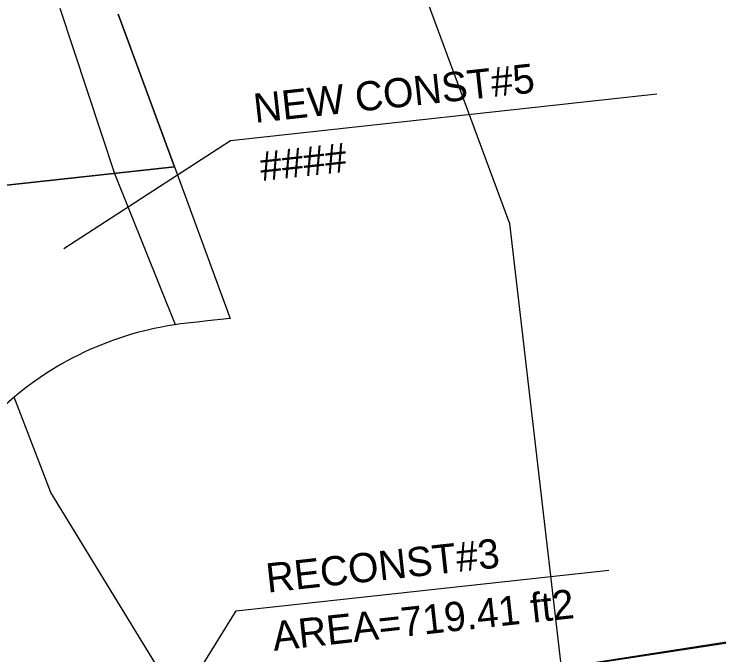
# Model space of a CAD drawing. Extents: x 1509538 to 1510847, y 401283 to 402022.
# Drawn here: x 1509818.6 to 1509886.2, y 401626.4 to 401687.8 of the extents above; entities that cross this region are included whole.
import ezdxf

# ---------------------------------------------------------------- set-up
doc = ezdxf.new("R2010")
doc.units = 0
for name, color, linetype in [('LAWE_P_T', 7, 'Continuous'), ('Level 24', 7, 'Continuous'), ('Level 25', 7, 'Continuous'), ('Level 3', 7, 'Continuous'), ('Level 4', 7, 'Continuous'), ('Level 5', 7, 'Continuous'), ('Level 7', 7, 'Continuous')]:
    doc.layers.add(name, color=color, linetype=linetype)

msp = doc.modelspace()

# ---------------------------------------------------------------- linework, layer by layer
at = {"layer": 'LAWE_P_T'}
for points in [[(1509823.397, 401665.344), (1509839.375, 401675.681), (1509880.206, 401680.132)], [(1509821.018, 401600.097), (1509839.911, 401630.638), (1509875.612, 401634.53)]]:
    msp.add_lwpolyline(points, dxfattribs=at)
at = {"layer": 'Level 24'}
msp.add_lwpolyline([(1509829.75, 401765.911), (1509866.097, 401667.732), (1509876.615, 401577.466), (1509875.566, 401568.188), (1509883.853, 401563.183), (1509866.769, 401506.877), (1509856.531, 401476.729), (1509809.074, 401412), (1509809.101, 401403.538), (1509796.557, 401386.395), (1509783.485, 401379.525), (1509778.168, 401371.598), (1509774.096, 401368.359), (1509767.585, 401349.346), (1509764.231, 401344.649), (1509737.941, 401349.46)], dxfattribs=at)
at = {"layer": 'Level 25'}
msp.add_lwpolyline([(1510026.788, 401648.904), (1510037.691, 401640.619), (1510051.798, 401629.899), (1510058.051, 401624.503), (1509984.136, 401613.929), (1509867.795, 401596.154), (1509863.727, 401624.032)], close=True, dxfattribs=at)
at = {"layer": 'Level 3'}
msp.add_lwpolyline([(1509823.042, 401688.327), (1509828.278, 401672.51), (1509834.078, 401658.053), (1509834.087, 401658.032), (1509834, 401658.02), (1509833.385, 401657.921), (1509832.772, 401657.81), (1509832.062, 401657.666), (1509831.554, 401657.552), (1509831.019, 401657.422), (1509830.473, 401657.28), (1509829.89, 401657.115), (1509829.31, 401656.939), (1509828.733, 401656.752), (1509828.16, 401656.553), (1509827.591, 401656.344), (1509827.026, 401656.123), (1509826.466, 401655.891), (1509825.911, 401655.649), (1509825.36, 401655.395), (1509824.814, 401655.131), (1509824.274, 401654.856), (1509823.739, 401654.571), (1509823.209, 401654.275), (1509822.686, 401653.969), (1509822.169, 401653.653), (1509821.658, 401653.326), (1509821.153, 401652.99), (1509820.403, 401652.463), (1509819.81, 401652.023), (1509819.203, 401651.549), (1509818.648, 401651.093)], dxfattribs=at)
at = {"layer": 'Level 4'}
for points in [[(1510068.151, 401655.21), (1510017.641, 401647.51), (1509967.631, 401640.04), (1509894.451, 401628.81), (1509861.081, 401623.62)], [(1509818.648, 401651.093), (1509817.594, 401650.166), (1509817.117, 401649.717), (1509816.54, 401649.147), (1509816.084, 401648.676), (1509815.468, 401648.006), (1509814.978, 401647.444)], [(1509863.366, 401606.462), (1509861.826, 401615.769), (1509838.993, 401621.028), (1509832.572, 401624.959), (1509822.152, 401641.967), (1509818.648, 401651.093)]]:
    msp.add_lwpolyline(points, dxfattribs=at)
at = {"layer": 'Level 5'}
for p, q in [((1509828.611, 401687.769), (1509834.002, 401673.134)), ((1509834.002, 401673.134), (1509828.611, 401687.769)), ((1509834.002, 401673.134), (1509774.898, 401666.69)), ((1509774.898, 401666.69), (1509834.002, 401673.134))]:
    msp.add_line(p, q, dxfattribs=at)
at = {"layer": 'Level 7'}
for p, q in [((1509774.898, 401666.69), (1509834, 401673.138)), ((1509834, 401673.138), (1509839.345, 401658.628)), ((1509837.164, 401658.39), (1509836.17, 401658.282)), ((1509839.345, 401658.628), (1509837.164, 401658.39)), ((1509832.062, 401657.666), (1509831.554, 401657.552)), ((1509832.772, 401657.81), (1509832.062, 401657.666)), ((1509833.385, 401657.921), (1509832.772, 401657.81)), ((1509834, 401658.02), (1509833.385, 401657.921)), ((1509834.616, 401658.106), (1509834, 401658.02)), ((1509835.235, 401658.18), (1509834.616, 401658.106)), ((1509836.17, 401658.282), (1509835.235, 401658.18)), ((1509829.89, 401657.115), (1509829.31, 401656.939)), ((1509830.473, 401657.28), (1509829.89, 401657.115)), ((1509831.019, 401657.422), (1509830.473, 401657.28)), ((1509831.554, 401657.552), (1509831.019, 401657.422)), ((1509827.591, 401656.344), (1509827.026, 401656.123)), ((1509828.16, 401656.553), (1509827.591, 401656.344)), ((1509828.733, 401656.752), (1509828.16, 401656.553)), ((1509829.31, 401656.939), (1509828.733, 401656.752)), ((1509825.911, 401655.649), (1509825.36, 401655.395)), ((1509826.466, 401655.891), (1509825.911, 401655.649)), ((1509827.026, 401656.123), (1509826.466, 401655.891)), ((1509824.814, 401655.131), (1509824.274, 401654.856)), ((1509825.36, 401655.395), (1509824.814, 401655.131)), ((1509823.209, 401654.275), (1509822.686, 401653.969)), ((1509823.739, 401654.571), (1509823.209, 401654.275)), ((1509824.274, 401654.856), (1509823.739, 401654.571)), ((1509822.169, 401653.653), (1509821.658, 401653.326)), ((1509822.686, 401653.969), (1509822.169, 401653.653)), ((1509821.153, 401652.99), (1509820.403, 401652.463)), ((1509821.658, 401653.326), (1509821.153, 401652.99)), ((1509820.403, 401652.463), (1509819.81, 401652.023)), ((1509819.203, 401651.549), (1509818.648, 401651.093)), ((1509819.81, 401652.023), (1509819.203, 401651.549))]:
    msp.add_line(p, q, dxfattribs=at)

# ---------------------------------------------------------------- texts
at = {"layer": 'LAWE_P_T'}
for s, height, p in [('NEW CONST#5', 2.79999, (1509841.738, 401677.347)), ('####', 2.8, (1509842.345, 401671.78)), ('RECONST#3', 2.8, (1509842.933, 401632.375)), ('AREA=719.41 ft2', 2.79999, (1509843.54, 401626.808))]:
    msp.add_text(s, height=height, rotation=6.2219, dxfattribs=at).set_placement(p)

doc.saveas('drawing.dxf')
